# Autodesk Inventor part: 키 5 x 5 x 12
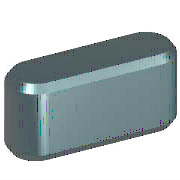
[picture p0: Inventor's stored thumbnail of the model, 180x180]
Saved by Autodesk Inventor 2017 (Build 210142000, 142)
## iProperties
Created: 2012-02
Part Number: 키 5 x 5 x 12
Material: 강철, 연강
Description: 키 및 해당 키홈
Document SubType Name: Modeling
Standard: KS B 1311
Designer: mduedu
Standards Organization: KS
Language: ko-KR
Size Designation: 5 x 5 x 12
Categories: <MemberInstance><Categories><Category DisplayName="샤프트 부품" InternalName="7f7aeb1f-a693-4053-b835-cee3144e0d98" Mnemonic="SHFT"><Category DisplayName="키" Interna
Density: 1 g/cm^3
Appearance: 노란색
IsCustomPart: 1
Author: mduedu
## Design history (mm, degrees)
workplane "Work Plane1"
workplane "Work Plane2"
sketch "스케치1"
  geometry: L1 (2.5, 2.5)-(9.5, 2.5); L2 (9.5, -2.5)-(2.5, -2.5); L3 (0, 9.4)-(0, -7.4) reference; L4 (-5, 0)-(30, 0) reference; L5 (12, 0)-(12, 7); A1 r 2.5 centre (2.5, 0) between (2.5, 2.5) and (2.5, -2.5); A2 r 2.5 centre (9.5, 0) between (9.5, -2.5) and (9.5, 2.5)
  constraints: 6 end point, 5 point on circle, 4 tangent, 3 point on line, 2 centre point, 1 horizontal, 1 parallel, 1 perpendicular
  dimensions: "d0" = 2.5 radius of A1 (= 0.5 x PB); "d13" = 2.5 radius of A2 (= 0.5 x PB); "d14" = 12 distance between parallel lines of L5 L3 (= NLG)
extrude "본체1" new body sketch "스케치1" taper "d3" = 0 deg; stored distance "d4" = 10
workplane "Work Plane3"
body "Solid1"
chamfer "모따기1" distance "d8" = 0.4 (= PHH); stored, may be unused: second distance "d9" = 0.4 (= PHH), angle "d15" = 45 deg
other parameters: "d1" = -3 (= -PNT), "d2" = 2 (= PH - PNT), "NLG" = 12 [user parameter; used in 3 equation terms], "PB" = 5 [user parameter; used in 2 equation terms], "PNT" = 3 [user parameter; used in 2 equation terms], "PH" = 5 [user parameter; used in 1 equation term], "PHH" = 0.4 [user parameter; used in 2 equation terms], "d10" = 0, "d16" = 0, "d17" = 0, "d18" = 0, "WDMIN" = 12 [user parameter], "PLB2" = 12 (= NLG) [user parameter], "WDMAX" = 17 [user parameter], "PLB1" = 12 (= NLG) [user parameter], "RR" = 0.16 [user parameter], "PUEB" = 2.3 [user parameter]
